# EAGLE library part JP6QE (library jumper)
JUMPER
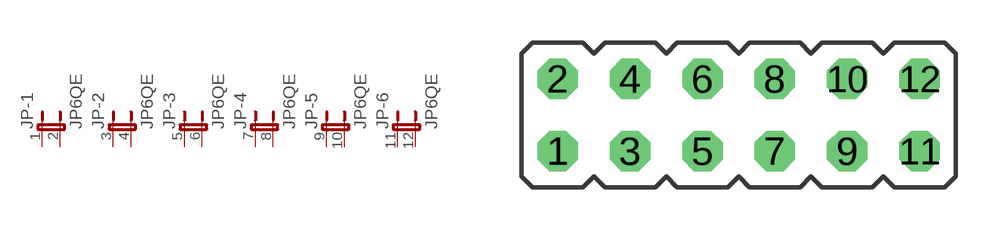
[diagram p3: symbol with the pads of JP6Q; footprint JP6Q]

Designator prefix JP; gates -1=JP2E -2=JP2E -3=JP2E -4=JP2E -5=JP2E -6=JP2E

## JP6QE  [JP6Q]
1  -1:1  pas
2  -1:2  pas
3  -2:1  pas
4  -2:2  pas
5  -3:1  pas
6  -3:2  pas
7  -4:1  pas
8  -4:2  pas
9  -5:1  pas
10  -5:2  pas
11  -6:1  pas
12  -6:2  pas

## Footprint JP6Q (pad centres in mm)
JUMPER
drill 0.914 octagon: 1 -6.35,-1.27; 2 -6.35,1.27; 3 -3.81,-1.27; 4 -3.81,1.27; 5 -1.27,-1.27; 6 -1.27,1.27; 7 1.27,-1.27; 8 1.27,1.27; 9 3.81,-1.27; 10 3.81,1.27; 11 6.35,-1.27; 12 6.35,1.27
